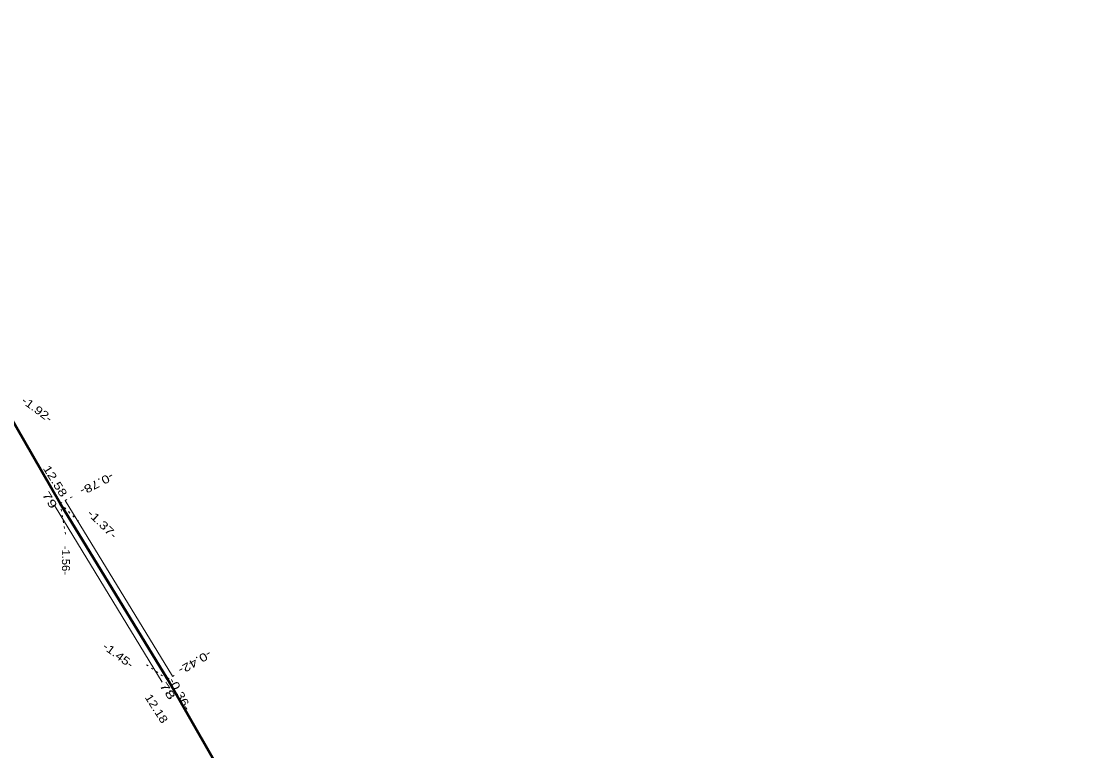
# Model space of a CAD drawing. Extents: x -603113 to -602961, y -1157278 to -1156712.
# Drawn here: x -603061.3 to -603008.1, y -1156787.6 to -1156751.2 of the extents above; entities that cross this region are included whole.
import ezdxf
from ezdxf.enums import TextEntityAlignment as Align

# ---------------------------------------------------------------- set-up
doc = ezdxf.new("R2010")
doc.units = 0
doc.header["$LTSCALE"] = 0.16
doc.header["$PDMODE"] = 32
doc.header["$PDSIZE"] = 0.08
doc.linetypes.add('DOTTED', pattern=[1.5, 0.3, -1.2])
for name, color, linetype, lineweight in [('12', 7, 'Continuous', 53), ('14', 7, 'DOTTED', 13), ('15', 7, 'Continuous', 13), ('17', 7, 'Continuous', 13)]:
    doc.layers.add(name, color=color, linetype=linetype, lineweight=lineweight)
doc.layers.add('35', color=7, linetype='Continuous')

msp = doc.modelspace()

# ---------------------------------------------------------------- linework, layer by layer
at = {"layer": '12'}
for points in [[(-603059.389, -1156775.282), (-603062.935, -1156769.141), (-603065.821, -1156762.81), (-603067.909, -1156756.453), (-603068.959, -1156752.425), (-603069.846, -1156751.19), (-603080.22, -1156753.11)], [(-603008.05, -1156862.95), (-603013.08, -1156859.75), (-603014.31, -1156857.03), (-603020.32, -1156843.12), (-603025.746, -1156832.154), (-603033.325, -1156818.288), (-603040.317, -1156805.906), (-603047.333, -1156795.776), (-603054.033, -1156784.062), (-603059.389, -1156775.282)]]:
    msp.add_lwpolyline(points, dxfattribs=at)
at = {"layer": '14'}
for p, q in [((-603059.389, -1156775.282), (-603058.408, -1156776.236)), ((-603054.033, -1156784.062), (-603055.222, -1156783.232))]:
    msp.add_line(p, q, dxfattribs=at)
for points in [[(-603059.12, -1156776.82), (-603059.389, -1156775.282), (-603058.714, -1156774.896)], [(-603054.183, -1156783.738), (-603054.033, -1156784.062), (-603053.662, -1156783.865)]]:
    msp.add_lwpolyline(points, dxfattribs=at)
at = {"layer": '15'}
for p in [(-603059.389, -1156775.282), (-603054.033, -1156784.062)]:
    msp.add_point(p, dxfattribs=at)
at = {"layer": '17'}
for p, q in [((-603059.645, -1156775.438), (-603054.289, -1156784.218)), ((-603059.132, -1156775.125), (-603053.776, -1156783.905))]:
    msp.add_line(p, q, dxfattribs=at)

# ---------------------------------------------------------------- texts
at = {"layer": '14'}
for s, rotation, width, p in [('-1.92-', 323.593, 1.25, (-603061.36, -1156770.219)), ('-0.78-', 207.199, 1.3, (-603056.837, -1156773.708)), ('-1.37-', 315.606, 1.3, (-603058.065, -1156775.816)), ('-1.56-', 270, 1.05, (-603059.3, -1156777.39)), ('-1.45-', 323.586, 1.25, (-603057.307, -1156782.503)), ('-0.42-', 210.422, 1.3, (-603051.97, -1156782.586)), ('-0.36-', 297.477, 1.25, (-603053.984, -1156784.116))]:
    msp.add_text(s, height=0.4, rotation=rotation, dxfattribs=dict(at, width=width)).set_placement(p)
at = {"layer": '15'}
for s, rotation, width, p in [('79', 301.482, 1.5, (-603060.314, -1156774.829)), ('78', 304.338, 1.55, (-603054.449, -1156784.375))]:
    msp.add_text(s, height=0.4, rotation=rotation, dxfattribs=dict(at, width=width)).set_placement(p)
at = {"layer": '35'}
for s, rotation, width, p in [('12.58', 301.882, 1.3, (-603059.8069, -1156774.2629)), ('12.18', 302.712, 1.2, (-603054.7474, -1156785.6369))]:
    msp.add_text(s, height=0.4, rotation=rotation, dxfattribs=dict(at, width=width)).set_placement(p, align=Align.CENTER)

doc.saveas('drawing.dxf')
